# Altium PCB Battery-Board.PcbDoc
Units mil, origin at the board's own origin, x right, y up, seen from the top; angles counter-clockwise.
Board outline 3775.2 x 3550 mil, 2 copper layers (Top Layer, Bottom Layer); 0 components, 0 nets, 4 pads, 0 vias.
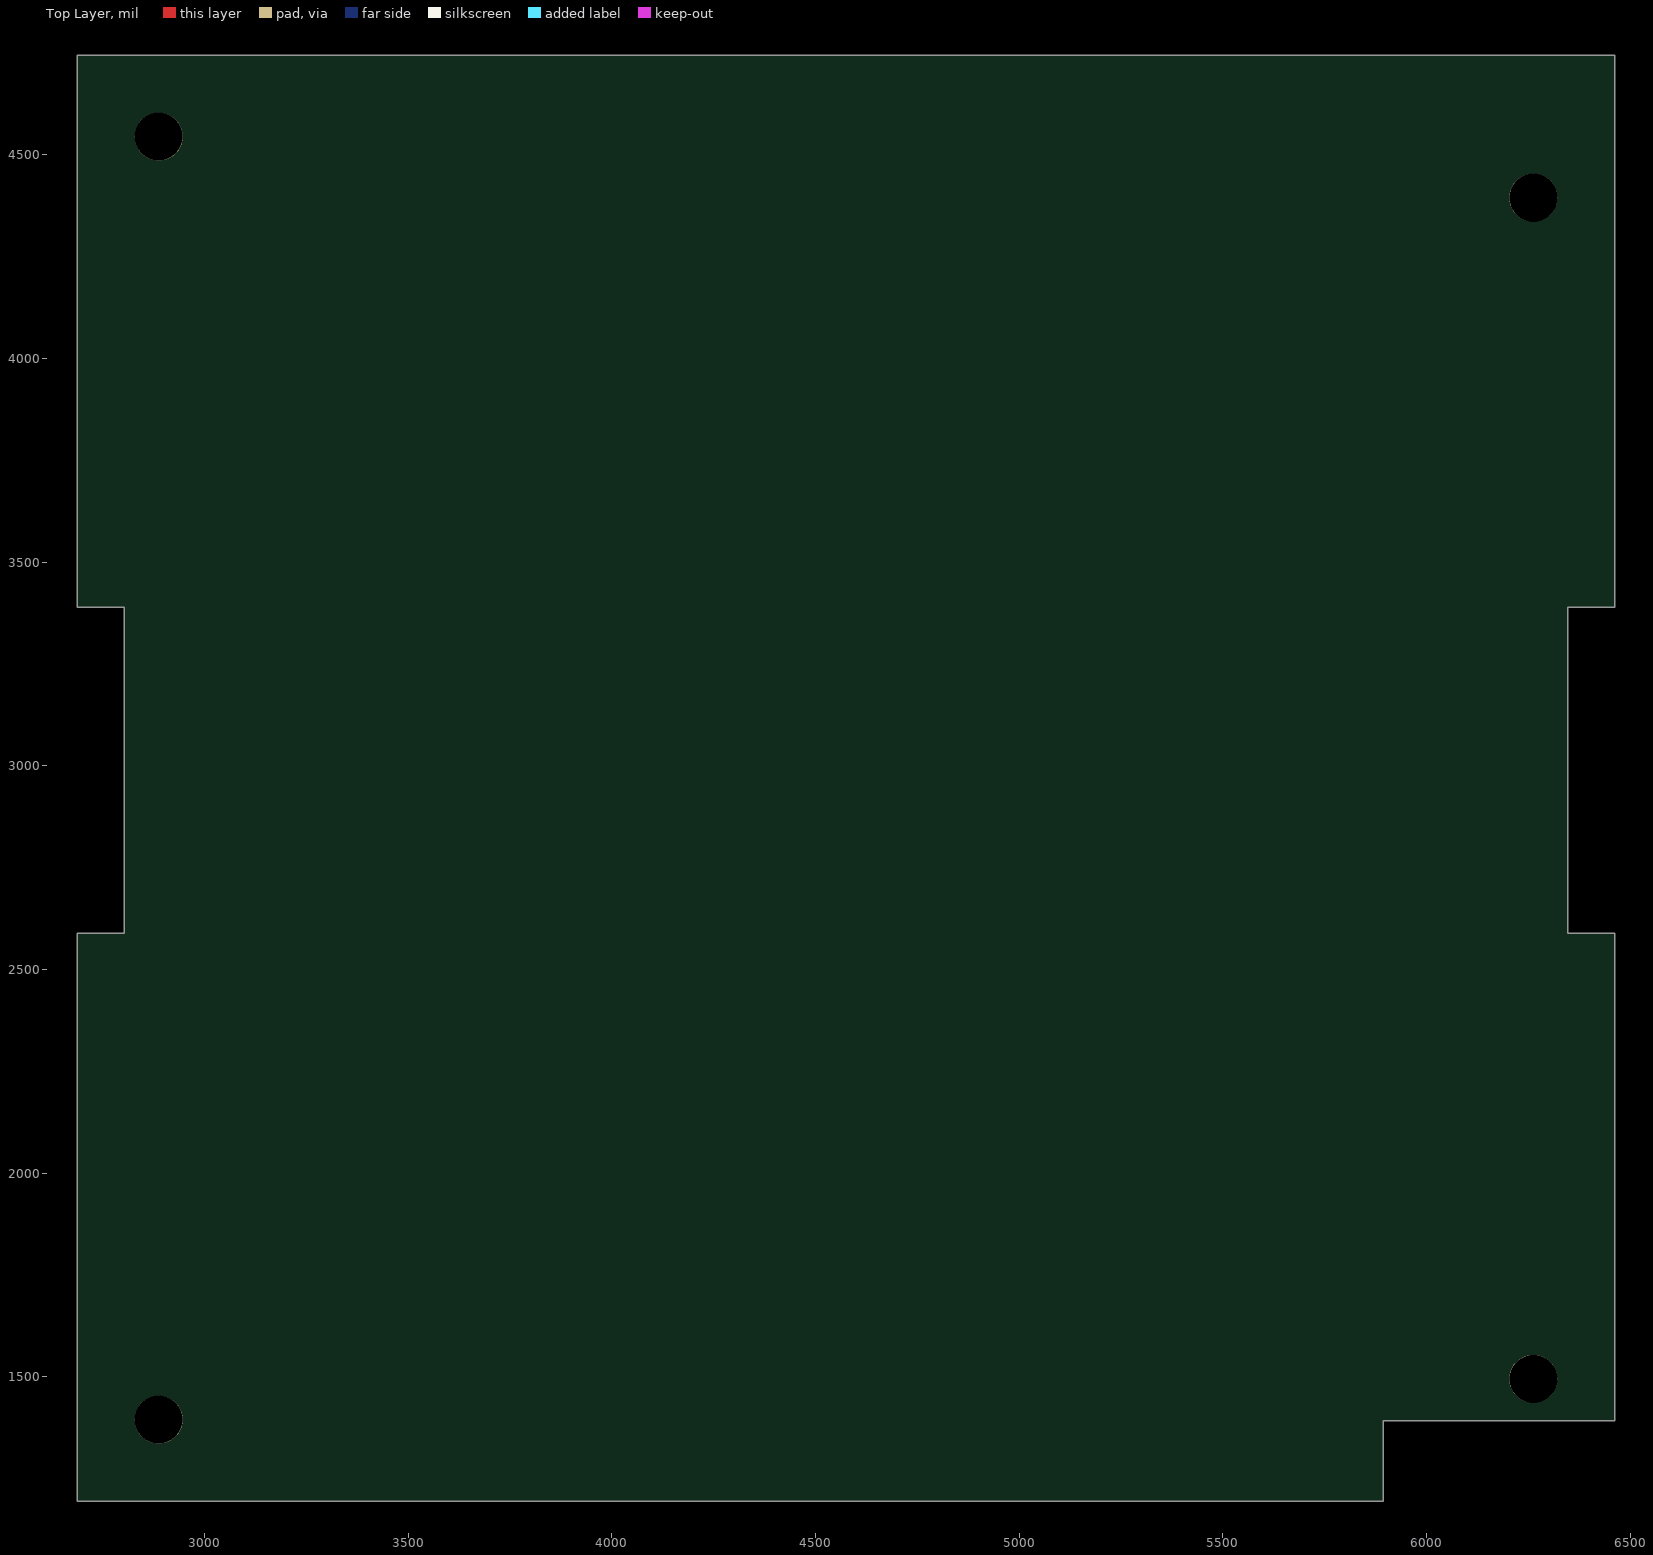
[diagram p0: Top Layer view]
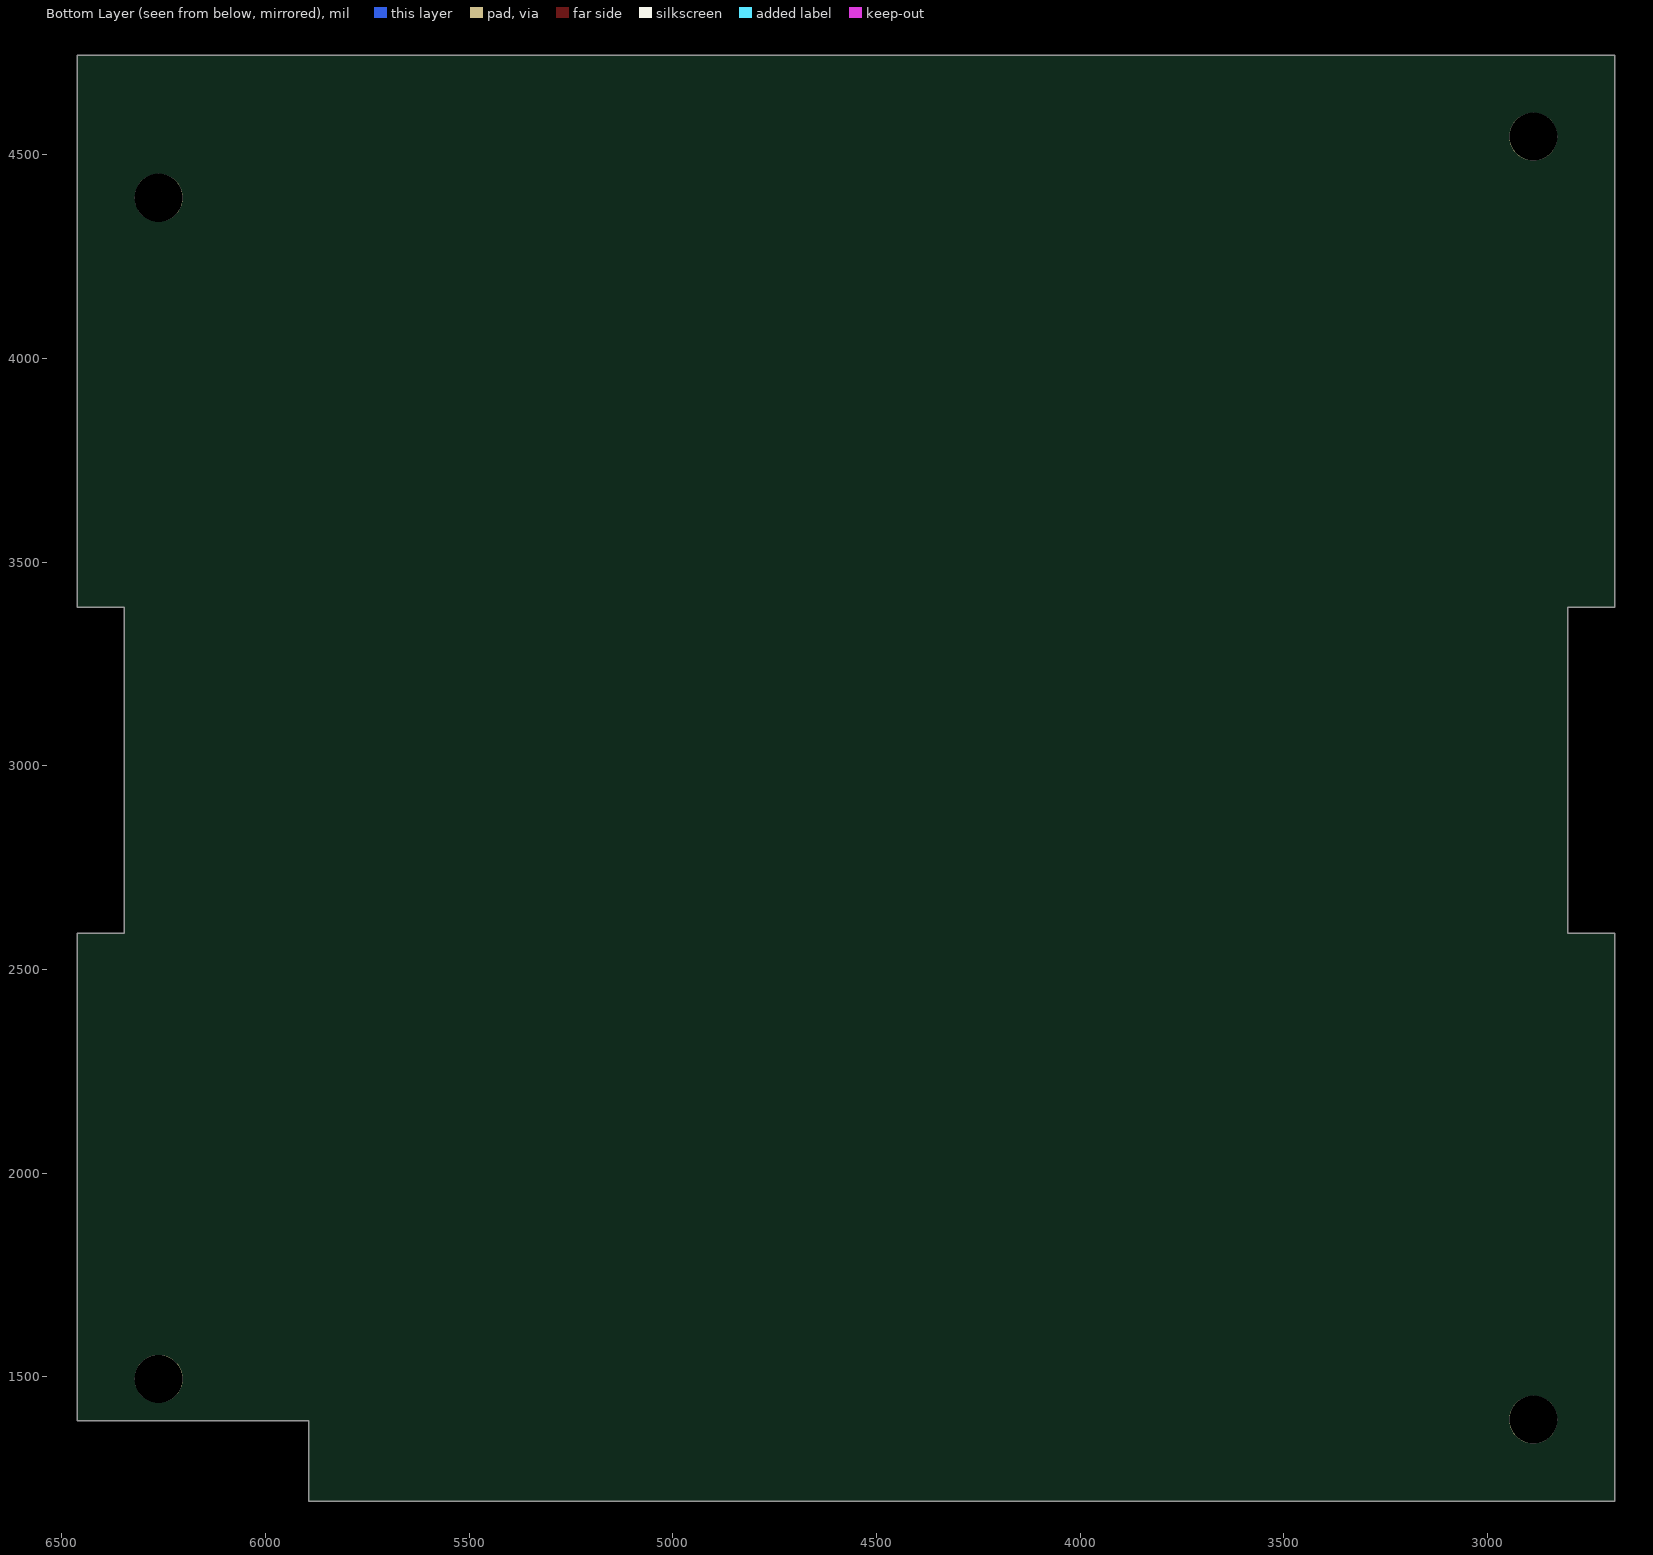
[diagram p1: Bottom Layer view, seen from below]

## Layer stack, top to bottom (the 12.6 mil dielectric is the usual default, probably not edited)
Top Solder: solder mask 0.4, Solder Resist, Dk 3.5
Top Layer: signal copper 1.4
Dielectric 1: dielectric 12.6, FR-4, Dk 4.8
Bottom Layer: signal copper 1.4
Bottom Solder: solder mask 0.4, Solder Resist, Dk 3.5

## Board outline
6462.6,3389.72 6462.6,4745 2687.4,4745 2687.4,3389.72 2802.4,3389.72 2802.4,2588.9 2687.4,2588.9 2687.4,1195 5894.55,1195 5894.55,1391.66 6462.6,1391.66 6462.6,2588.9 6347.6,2588.9 6347.6,3389.72

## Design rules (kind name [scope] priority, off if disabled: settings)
Clearance [All] p1: gap=10
PolygonConnect [All] p1: connectstyle=Relief reliefconductorwidth=10 reliefentries=4 polygonreliefangle="90 Angle" airgapwidth=10
RoutingVias [All] p1: holewidth=28 width=50 viastyle="Through Hole" minholewidth=28 minwidth=50 maxholewidth=28 maxwidth=50
SolderMaskExpansion [All] p1: expansion=4
Width [All] p1: maxlimit=10 minlimit=10 preferedwidth=10
30 further rules are at their usual default settings.

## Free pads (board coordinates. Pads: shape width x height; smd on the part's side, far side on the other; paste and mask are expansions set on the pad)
  round 118.11 hole 118.11: 1(2887.4,1395) 1(2887.4,4545) 1(6262.6,1495) 1(6262.6,4395)

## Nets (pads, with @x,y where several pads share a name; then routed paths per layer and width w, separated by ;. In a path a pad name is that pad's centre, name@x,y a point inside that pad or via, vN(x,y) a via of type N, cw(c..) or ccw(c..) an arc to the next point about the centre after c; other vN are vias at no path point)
